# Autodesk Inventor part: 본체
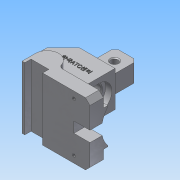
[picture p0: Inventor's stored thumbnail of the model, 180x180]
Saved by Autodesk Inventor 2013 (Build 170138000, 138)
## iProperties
Created: 2016-11
Part Number: 본체
Material: 알루미늄 6061
Document SubType Name: Modeling
Designer: Administrator
Density: 2.71 g/cm^3
Mass: 462.813 g
Surface Area: 317.449 cm^2
Volume: 170.78 cm^3
Author: Administrator
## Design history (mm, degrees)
sketch "스케치1"
  geometry: L1 (0, 0)-(63, 0); L2 (63, 0)-(63, 20); L3 (63, 20)-(0, 20); L4 (0, 20)-(0, 0)
  constraints: 8 end point, 2 perpendicular, 1 horizontal, 1 parallel
  dimensions: "d0" = 63 distance of L1.start L1.end; "d1" = 20 distance of L1.end L2.end
extrude "돌출1" new body sketch "스케치1" distance "d2" = 70; taper "d3" = 0 deg
sketch "스케치2"
  geometry: L1 (0, 0)-(63, 0) reference; L2 (0, 20)-(0, 0) reference; L3 (0, 0)-(0, 15); L4 (-13, 15)-(-13, 0); L5 (-13, 0)-(-10, 0); L6 (-10, 0)-(-10, 7); L7 (-10, 7)-(10, 7); L8 (10, 7)-(10, 0); A1 r 13 centre (0, 15) between (10, 6.693) and (-13, 15)
  constraints: 12 end point, 4 perpendicular, 3 point on line, 2 point on circle, 1 centre point, 1 coincident, 1 parallel, 1 tangent
extrude "돌출2" join sketch "스케치2" distance "d9" = 70; taper "d10" = 0 deg
sketch "스케치3"
  geometry: L1 (0, 7)-(0, 0) reference; L2 (0, 0)-(63, 0) reference; L3 (-10, 0)-(10, 0); L4 (10, 0)-(10, 7); L5 (10, 7)-(0, 7); L6 (0, 7)-(0, 0)
  constraints: 8 end point, 1 collinear, 1 perpendicular, 1 point on line
  dimensions: "d11" = 20 distance of L3.start L3.end; "d12" = 7 distance of L3.end L4.end
extrude "돌출3" cut sketch "스케치3" distance "d13" = 70; taper "d14" = 0 deg
node "작업 평면1"
sketch "스케치4"
  geometry: L1 (10, 7)-(-10, 7) reference; L2 (-10, 7)-(-10, 0) reference; L3 (-10, 0)-(-13, 0) reference; L4 (-13, 0)-(-13, 15) reference; L5 (12, 20)-(63, 20) reference; L6 (63, 20)-(63, 0) reference; L7 (63, 0)-(10, 0) reference; L8 (10, 0)-(10, 7) reference; L9 (31, 60)-(31, 20); L10 (-9, 60)-(-27, 42); L11 (-27, 42)-(-27, 12); L12 (-27, 12)-(-13, 12); L13 (-9, 60)-(31, 60); A1 r 13 centre (0, 15) between (12, 20) and (-13, 15) reference; 1 further point
  constraints: 10 end point, 2 perpendicular, 2 point on line, 1 parallel
extrude "돌출4" join sketch "스케치4" stored distance "d23" = 40; taper "d24" = 0 deg
sketch "스케치5"
  geometry: L1 (63, 0)-(63, 20) reference; L2 (63, 20)-(12, 20) reference; L3 (-13, 15)-(-13, 0) reference; L4 (63, 15)-(13, 15); L5 (12, 20)-(63, 20); L6 (63, 20)-(63, 15); L7 (13, 15)-(63, 15); A1 r 13 centre (0, 15) between (12, 20) and (-13, 15) reference; A2 r 13 centre (0, 15) between (13, 15) and (12, 20); 1 further point
  constraints: 10 end point, 3 collinear, 2 point on circle, 1 centre point, 1 coincident, 1 point on line
extrude "돌출5" cut sketch "스케치5" distance "d26" = 15; taper "d27" = 0 deg
sketch "스케치6"
  geometry: L1 (-10, 7)-(10, 7) reference; L2 (13, 0)-(13, 15) reference; L3 (-12, 20)-(-63, 20) reference; L4 (-63, 20)-(-63, 0) reference; L5 (-10, 0)-(-10, 7) reference; L6 (-63, 0)-(-63, 7); L7 (-63, 15)-(-13, 15); A1 r 13 centre (0, 15) between (13, 15) and (-12, 20) reference; A2 r 13 centre (0, 15) between (-10, 6.693) and (13, 15); A3 r 13 centre (0, 15) between (-12, 20) and (-13, 15); 1 further point
  constraints: 6 end point, 4 point on circle, 3 point on line, 2 centre point, 1 coincident, 1 perpendicular
  dimensions: "d28" = 15 distance of L4.end L7.start
extrude "돌출6" cut sketch "스케치6" distance "d29" = 15; taper "d30" = 0 deg
sketch "스케치7"
  geometry: L1 (0, -5)-(0, -8) reference; L2 (0, -8)-(40, -8) reference; L3 (40, -8)-(40, -5) reference; L4 (40, -5)-(55, -5) reference; L5 (55, -20)-(55, -5) reference; L6 (-15, -20)-(55, -20) reference; L7 (-15, -5)-(-15, -20) reference; L8 (-15, -5)-(0, -5) reference; L9 (20, -20)-(20, 22); C1 r 14.5 at (20, 22); 1 further point
  constraints: 2 end point, 1 centre point, 1 coincident, 1 midpoint, 1 perpendicular
  dimensions: "d31" = 42 distance of L9.start L9.end; "d32" = 29 diameter of C1
extrude "돌출7" cut sketch "스케치7" distance "d33" = 7; taper "d34" = 0 deg
sketch "스케치8"
  geometry: C1 r 14.5 at (0, 0) reference; C2 r 10 at (0, 0); 1 further point
  constraints: 1 centre point, 1 coincident
  dimensions: "d35" = 20 diameter of C2
extrude "돌출8" cut sketch "스케치8" stored distance "d36" = 7; taper "d37" = 0 deg
sketch "스케치9"
  geometry: L1 (55, 60)-(15, 60) reference; L2 (15, 20)-(15, 60) reference; L3 (55, 20)-(15, 20) reference; L4 (55, 60)-(55, 20) reference; C1 r 14.5 at (35, 42) reference; C2 r 29 at (35, 42)
  constraints: 1 centre point, 1 coincident
  dimensions: "d38" = 58 diameter of C2
extrude "돌출9" cut sketch "스케치9" distance "d39" = 18; taper "d40" = 0 deg
sketch "스케치10"
  geometry: L1 (0, 0)-(70, 0) reference; L2 (35, 0)-(41, 0); L3 (41, 0)-(41, 13.627); L4 (35, 0)-(29, 0); L5 (29, 0)-(29, 13.627); A1 r 29 centre (35, 42) between (16.106, 20) and (53.894, 20) reference
  constraints: 8 end point, 2 perpendicular, 2 point on circle, 2 point on line, 1 midpoint
extrude "돌출10" cut sketch "스케치10" distance "d43" = 18; taper "d44" = 0 deg
sketch "스케치11"
  geometry: L1 (-22, 55)-(-22, 15) reference; L2 (18, 15)-(-22, 15) reference; L3 (18, 55)-(18, 15) reference; L4 (-22, 55)-(18, 55) reference; 2 further points
hole "구멍1" sketch "스케치11" at (32, 7.5) diameter "d47" = 3.459; stored, may be unused: countersink angle "d51" = 90 deg, drill point angle "d53" = 118 deg; dims "d48" = 20, "d49" = 4, "d50" = 2, "d52" = 8
sketch "스케치12"
  geometry: L1 (-13, 12)-(-13, 15) reference; L2 (-13, 12)-(-27, 12) reference; L3 (-27, 12)-(-27, 42) reference; L4 (-27, 42)-(-9, 60) reference; L5 (-9, 60)-(31, 60) reference; L6 (31, 60)-(31, 20) reference; L7 (63, 20)-(31, 20) reference; L8 (63, 15)-(63, 20) reference; L9 (13, 15)-(63, 15) reference; L10 (31, 60)-(26, 60); L11 (13, 15)-(63, 15) reference; L12 (63, 15)-(63, 0) reference; L13 (63, 0)-(10, 0) reference; L14 (10, 0)-(10, 7) reference; L15 (10, 7)-(-10, 7) reference; L16 (-10, 7)-(-10, 0) reference; L17 (-10, 0)-(-13, 0) reference; L18 (-13, 0)-(-13, 15) reference; L19 (26, 90)-(26, 60); L20 (26, 90)-(1, 90); L21 (1, 90)-(1, 60); A1 r 13 centre (0, 15) between (13, 15) and (-13, 15) reference; A2 r 13 centre (0, 15) between (13, 15) and (-13, 15) reference; 1 further point
  constraints: 8 end point, 2 perpendicular, 2 point on line
  dimensions: "d56" = 25 distance of L19.start L20.end
extrude "돌출11" join sketch "스케치12" stored distance "d57" = 20; taper "d58" = 0 deg
sketch "스케치13"
  geometry: L1 (26, 60)-(26, 90) reference; L2 (1, 90)-(1, 60) reference; L3 (26, 77)-(1, 77); C1 r 4 at (13.5, 77); 1 further point
  constraints: 2 end point, 2 point on line, 1 centre point, 1 midpoint
  dimensions: "d61" = 8 diameter of C1
extrude "돌출12" cut sketch "스케치13" distance "d62" = 20; taper "d63" = 0 deg
chamfer "모따기1" distance "d64" = 4; stored, may be unused: second distance "d65" = 2, angle "d66" = 45 deg
chamfer "모따기2" distance "d67" = 5; stored, may be unused: second distance "d68" = 2, angle "d69" = 45 deg
fillet "모깎기1" dims "d70" = 5, "d71" = 3
chamfer "모따기3" distance "d72" = 1; stored, may be unused: second distance "d73" = 2, angle "d74" = 45 deg
sketch "스케치14"
  geometry: L1 (-12.291, 46.916)-(24.291, 46.916); L2 (24.291, 46.916)-(24.291, 37.084); L3 (24.291, 37.084)-(-12.291, 37.084); L4 (-12.291, 37.084)-(-12.291, 46.916); 1 further point
  constraints: 2 other
feature "엠보싱1" sketch "스케치14" dims "d0" = 63, "d1" = 20, "d32" = 29, "d77" = 0.5, "d78" = 0
node "솔리드1"
mirror "대칭1"
node "투영된 루프1"
node "투영된 루프2"
node "투영된 루프3"
node "투영된 루프4"
node "투영된 루프5"
node "투영된 루프6"
other parameters: "d15" = -35
